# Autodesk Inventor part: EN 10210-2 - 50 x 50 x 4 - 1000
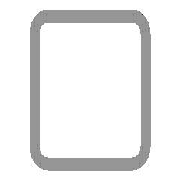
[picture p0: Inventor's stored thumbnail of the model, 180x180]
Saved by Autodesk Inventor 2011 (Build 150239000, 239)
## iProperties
_CCFamilyMember: 15
_CCFamilyDisplayName: DIN EN 10210-2 (Square) - Tube
_FrameMemberDoc: Frame Member File
_Version: 15.0.0
_GetPNFromCC: 1
Created: 2010-02
Part Number: EN 10210-2 - 50 x 50 x 4 - 1000
Material: Steel, Mild
Description: Tube 50*50*4
Document SubType Name: Modeling
Standard: DIN
Designer: PC
Standard Revision: 1997
Standards Organization: DIN
Language: en-US
Size Designation: 50 x 50 x 4
Categories: <MemberInstance><Categories><Category DisplayName="Structural Shapes" InternalName="089c4875-fa83-4c05-b084-43b9cc11f5ed" Mnemonic="GRDR"><CategoryParameter Dis
Stock Number: 50 x 50 x 4
Density: 7.86 g/cm^3
IsCustomPart: 1
G_L: 1000.000 mm
G_W: 50.000 mm
G_H: 50.000 mm
Author: PC
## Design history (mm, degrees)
node "Start plane"
node "End plane"
sketch "Sketch"
  geometry: L1 (-25, -19)-(-25, 19); L2 (-19, 25)-(19, 25); L3 (25, 19)-(25, -19); L4 (19, -25)-(-19, -25); L5 (-19, 21)-(19, 21); L6 (21, 19)-(21, -19); L7 (19, -21)-(-19, -21); L8 (-21, -19)-(-21, 19); L9 (0, 36.74)-(0, -36.74) reference; L10 (-36.74, 0)-(36.74, 0) reference; A1 r 6 centre (-19, -19) between (-25, -19) and (-19, -25); A2 r 6 centre (-19, 19) between (-19, 25) and (-25, 19); A3 r 6 centre (19, 19) between (25, 19) and (19, 25); A4 r 6 centre (19, -19) between (19, -25) and (25, -19); A5 r 2 centre (-19, 19) between (-19, 21) and (-21, 19); A6 r 2 centre (19, 19) between (21, 19) and (19, 21); A7 r 2 centre (19, -19) between (19, -21) and (21, -19); A8 r 2 centre (-19, -19) between (-21, -19) and (-19, -21)
  constraints: 16 end point, 16 point on circle, 8 centre point, 8 tangent, 4 parallel, 3 equal radius, 2 perpendicular, 7 other
  dimensions: "d7" = 6 radius of A1 (= G_IR); "d10" = 50 distance between parallel lines of L2 L4 (= G_H); "d11" = 50 distance between parallel lines of L1 L3 (= G_W); "d12" = 4 distance between parallel lines of L3 L6 (= G_T); "d15" = 25 distance between parallel lines of L2 L10 (= 0.5 x d10); "d16" = 25 distance between parallel lines of L9 L3 (= 0.5 x d11)
extrude "Body" new body sketch "Sketch" stored distance "d3" = 1000 (= G_L); taper "d4" = 0 deg
node "Driven Length"
  sketch "Sketch3"
    geometry: L1 (0, 0)-(10, 0) reference
    constraints: 2 end point, 1 horizontal
  workplane "Work Plane3"
  sketch "Sketch4"
    geometry: L1 (-2, 0)-(12, 0) reference; L2 (-2, 1000)-(12, 1000) reference
    dimensions: "d18" = 1000 distance between parallel lines of L1 L2 (derived)
body "Solid1"
other parameters: "G_W" = 50 [user parameter; used in 1 equation term], "G_H" = 50 [user parameter; used in 1 equation term], "G_T" = 4 [user parameter; used in 1 equation term], "G_IR" = 6 [user parameter; used in 1 equation term], "G_L" = 1000 (= d18) [user parameter; used in 1 equation term], "G_OFFSET_START" = 0 [user parameter; used in 1 equation term], "G_OFFSET_END" = 0 [user parameter; used in 1 equation term], "d13" = 0 (computed from G_OFFSET_START), "d17" = 90 deg
